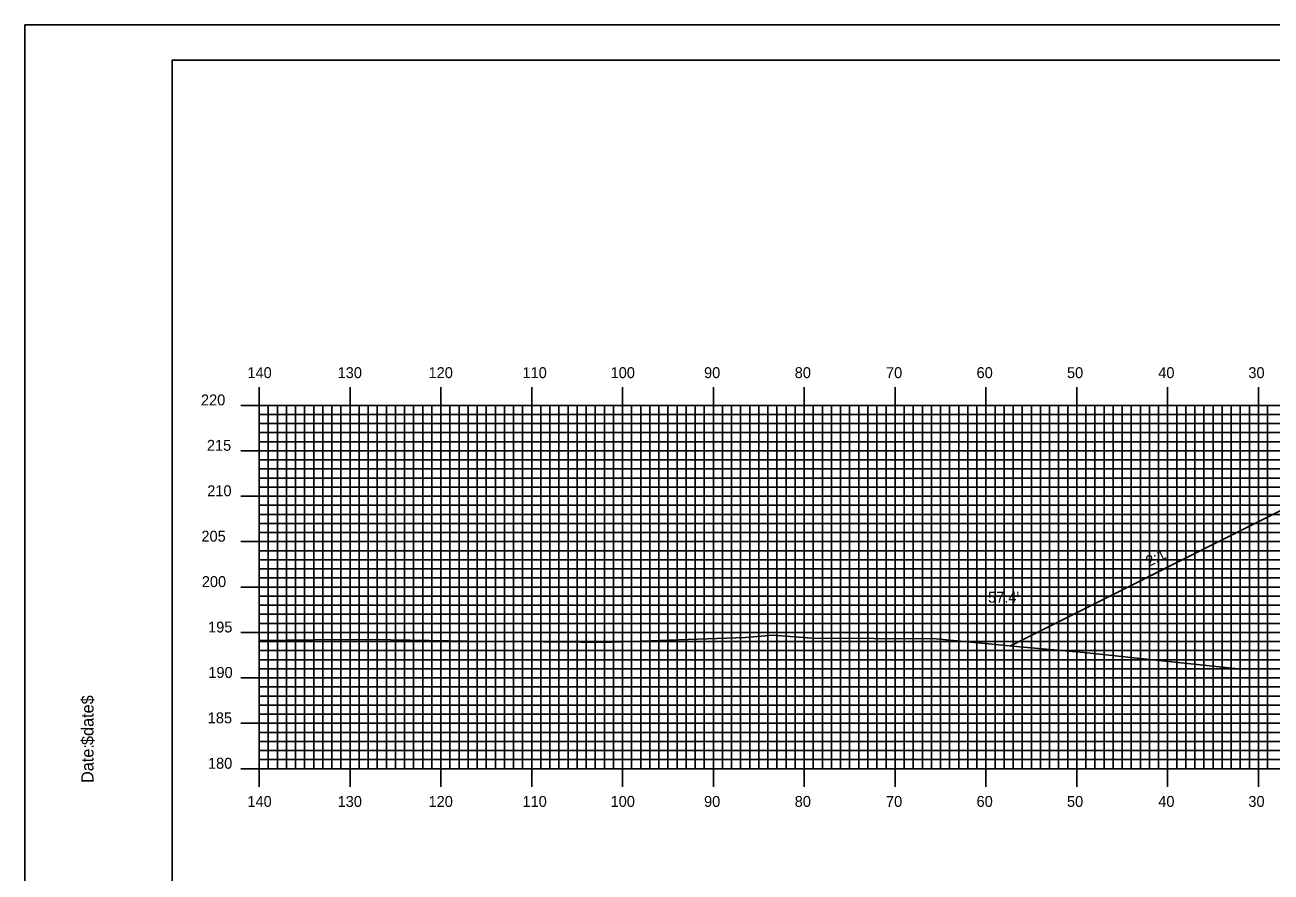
# Model space of a CAD drawing. Extents: x 1812948 to 1813291, y 442591 to 442811.
# Drawn here: x 1812947.7 to 1813084.9, y 442717.3 to 442810.5 of the extents above; entities that cross this region are included whole.
import ezdxf

# ---------------------------------------------------------------- set-up
doc = ezdxf.new("R2010")
doc.units = 0
for name, color, linetype in [('ANNOTATION', 7, 'Continuous'), ('BORDER', 7, 'Continuous'), ('D_Roadway_Centerline', 7, 'Continuous'), ('D_Roadway_SlopeLines', 7, 'Continuous'), ('D_Text_Standard', 7, 'Continuous'), ('H_V ANNOTATION', 7, 'Continuous'), ('MAJOR', 7, 'Continuous'), ('MINOR', 7, 'Continuous'), ('PLOT BOUNDARY', 7, 'Continuous'), ('S_Roadway_Centerline', 7, 'Continuous')]:
    doc.layers.add(name, color=color, linetype=linetype)

msp = doc.modelspace()

# ---------------------------------------------------------------- linework, layer by layer
at = {"layer": 'BORDER'}
msp.add_lwpolyline([(1812963.86, 442596.67), (1813283.86, 442596.67), (1813283.86, 442806.67), (1812963.86, 442806.67)], close=True, dxfattribs=at)
at = {"layer": 'D_Roadway_Centerline'}
msp.add_lwpolyline([(1813056.1, 442742.18), (1813085.25, 442756.76), (1813090.46, 442759.36), (1813093.46, 442759.42), (1813101.46, 442759.58), (1813113.46, 442759.01), (1813125.46, 442758.43), (1813133.46, 442758.05), (1813136.46, 442757.9), (1813141.99, 442755.14), (1813175.76, 442738.25)], dxfattribs=at)
at = {"layer": 'D_Roadway_SlopeLines'}
msp.add_lwpolyline([(1813090.46, 442759.36), (1813056.1, 442742.18)], dxfattribs=at)
at = {"layer": 'MAJOR'}
for p, q in [((1812973.46, 442770.67), (1812973.46, 442768.67)), ((1812983.46, 442770.67), (1812983.46, 442768.67)), ((1812993.46, 442770.67), (1812993.46, 442768.67)), ((1813003.46, 442770.67), (1813003.46, 442768.67)), ((1813013.46, 442770.67), (1813013.46, 442768.67)), ((1813023.46, 442770.67), (1813023.46, 442768.67)), ((1813033.46, 442770.67), (1813033.46, 442768.67)), ((1813043.46, 442770.67), (1813043.46, 442768.67)), ((1813053.46, 442770.67), (1813053.46, 442768.67)), ((1813063.46, 442770.67), (1813063.46, 442768.67)), ((1813073.46, 442770.67), (1813073.46, 442768.67)), ((1813083.46, 442770.67), (1813083.46, 442768.67)), ((1812971.45, 442768.67), (1812973.46, 442768.67)), ((1812973.46, 442768.67), (1813253.46, 442768.67)), ((1812973.46, 442728.67), (1812973.46, 442768.67)), ((1812973.46, 442728.67), (1812973.46, 442768.67)), ((1812973.46, 442768.67), (1813253.46, 442768.67)), ((1812983.46, 442728.67), (1812983.46, 442768.67)), ((1812993.46, 442728.67), (1812993.46, 442768.67)), ((1813003.46, 442728.67), (1813003.46, 442768.67)), ((1813013.46, 442728.67), (1813013.46, 442768.67)), ((1813023.46, 442728.67), (1813023.46, 442768.67)), ((1813033.46, 442728.67), (1813033.46, 442768.67)), ((1813043.46, 442728.67), (1813043.46, 442768.67)), ((1813053.46, 442728.67), (1813053.46, 442768.67)), ((1813063.46, 442728.67), (1813063.46, 442768.67)), ((1813073.46, 442728.67), (1813073.46, 442768.67)), ((1813083.46, 442728.67), (1813083.46, 442768.67)), ((1812971.45, 442763.67), (1812973.46, 442763.67)), ((1812973.46, 442763.67), (1813253.46, 442763.67)), ((1812971.45, 442758.67), (1812973.46, 442758.67)), ((1812973.46, 442758.67), (1813253.46, 442758.67)), ((1812971.45, 442753.67), (1812973.46, 442753.67)), ((1812973.46, 442753.67), (1813253.46, 442753.67)), ((1812971.45, 442748.67), (1812973.46, 442748.67)), ((1812973.46, 442748.67), (1813253.46, 442748.67)), ((1812971.45, 442743.67), (1812973.46, 442743.67)), ((1812973.46, 442743.67), (1813253.46, 442743.67)), ((1812971.45, 442738.67), (1812973.46, 442738.67)), ((1812973.46, 442738.67), (1813253.46, 442738.67)), ((1812971.45, 442733.67), (1812973.46, 442733.67)), ((1812973.46, 442733.67), (1813253.46, 442733.67)), ((1812971.45, 442728.67), (1812973.46, 442728.67)), ((1812973.46, 442728.67), (1813253.46, 442728.67)), ((1812973.46, 442728.67), (1813253.46, 442728.67)), ((1812973.46, 442726.66), (1812973.46, 442728.67)), ((1812983.46, 442726.66), (1812983.46, 442728.67)), ((1812993.46, 442726.66), (1812993.46, 442728.67)), ((1813003.46, 442726.66), (1813003.46, 442728.67)), ((1813013.46, 442726.66), (1813013.46, 442728.67)), ((1813023.46, 442726.66), (1813023.46, 442728.67)), ((1813033.46, 442726.66), (1813033.46, 442728.67)), ((1813043.46, 442726.66), (1813043.46, 442728.67)), ((1813053.46, 442726.66), (1813053.46, 442728.67)), ((1813063.46, 442726.66), (1813063.46, 442728.67)), ((1813073.46, 442726.66), (1813073.46, 442728.67)), ((1813083.46, 442726.66), (1813083.46, 442728.67))]:
    msp.add_line(p, q, dxfattribs=at)
at = {"layer": 'MINOR'}
for p, q in [((1812973.46, 442767.67), (1813253.46, 442767.67)), ((1812973.46, 442767.67), (1812975.46, 442767.67)), ((1812974.46, 442728.67), (1812974.46, 442768.67)), ((1812975.46, 442728.67), (1812975.46, 442768.67)), ((1812976.46, 442728.67), (1812976.46, 442768.67)), ((1812977.46, 442728.67), (1812977.46, 442768.67)), ((1812978.46, 442728.67), (1812978.46, 442768.67)), ((1812979.46, 442728.67), (1812979.46, 442768.67)), ((1812980.46, 442728.67), (1812980.46, 442768.67)), ((1812981.46, 442728.67), (1812981.46, 442768.67)), ((1812982.46, 442728.67), (1812982.46, 442768.67)), ((1812984.46, 442728.67), (1812984.46, 442768.67)), ((1812985.46, 442728.67), (1812985.46, 442768.67)), ((1812986.46, 442728.67), (1812986.46, 442768.67)), ((1812987.46, 442728.67), (1812987.46, 442768.67)), ((1812988.46, 442728.67), (1812988.46, 442768.67)), ((1812989.46, 442728.67), (1812989.46, 442768.67)), ((1812990.46, 442728.67), (1812990.46, 442768.67)), ((1812991.46, 442728.67), (1812991.46, 442768.67)), ((1812992.46, 442728.67), (1812992.46, 442768.67)), ((1812994.46, 442728.67), (1812994.46, 442768.67)), ((1812995.46, 442728.67), (1812995.46, 442768.67)), ((1812996.46, 442728.67), (1812996.46, 442768.67)), ((1812997.46, 442728.67), (1812997.46, 442768.67)), ((1812998.46, 442728.67), (1812998.46, 442768.67)), ((1812999.46, 442728.67), (1812999.46, 442768.67)), ((1813000.46, 442728.67), (1813000.46, 442768.67)), ((1813001.46, 442728.67), (1813001.46, 442768.67)), ((1813002.46, 442728.67), (1813002.46, 442768.67)), ((1813004.46, 442728.67), (1813004.46, 442768.67)), ((1813005.46, 442728.67), (1813005.46, 442768.67)), ((1813006.46, 442728.67), (1813006.46, 442768.67)), ((1813007.46, 442728.67), (1813007.46, 442768.67)), ((1813008.46, 442728.67), (1813008.46, 442768.67)), ((1813009.46, 442728.67), (1813009.46, 442768.67)), ((1813010.46, 442728.67), (1813010.46, 442768.67)), ((1813011.46, 442728.67), (1813011.46, 442768.67)), ((1813012.46, 442728.67), (1813012.46, 442768.67)), ((1813014.46, 442728.67), (1813014.46, 442768.67)), ((1813015.46, 442728.67), (1813015.46, 442768.67)), ((1813016.46, 442728.67), (1813016.46, 442768.67)), ((1813017.46, 442728.67), (1813017.46, 442768.67)), ((1813018.46, 442728.67), (1813018.46, 442768.67)), ((1813019.46, 442728.67), (1813019.46, 442768.67)), ((1813020.46, 442728.67), (1813020.46, 442768.67)), ((1813021.46, 442728.67), (1813021.46, 442768.67)), ((1813022.46, 442728.67), (1813022.46, 442768.67)), ((1813024.46, 442728.67), (1813024.46, 442768.67)), ((1813025.46, 442728.67), (1813025.46, 442768.67)), ((1813026.46, 442728.67), (1813026.46, 442768.67)), ((1813027.46, 442728.67), (1813027.46, 442768.67)), ((1813028.46, 442728.67), (1813028.46, 442768.67)), ((1813029.46, 442728.67), (1813029.46, 442768.67)), ((1813030.46, 442728.67), (1813030.46, 442768.67)), ((1813031.46, 442728.67), (1813031.46, 442768.67)), ((1813032.46, 442728.67), (1813032.46, 442768.67)), ((1813034.46, 442728.67), (1813034.46, 442768.67)), ((1813035.46, 442728.67), (1813035.46, 442768.67)), ((1813036.46, 442728.67), (1813036.46, 442768.67)), ((1813037.46, 442728.67), (1813037.46, 442768.67)), ((1813038.46, 442728.67), (1813038.46, 442768.67)), ((1813039.46, 442728.67), (1813039.46, 442768.67)), ((1813040.46, 442728.67), (1813040.46, 442768.67)), ((1813041.46, 442728.67), (1813041.46, 442768.67)), ((1813042.46, 442728.67), (1813042.46, 442768.67)), ((1813044.46, 442728.67), (1813044.46, 442768.67)), ((1813045.46, 442728.67), (1813045.46, 442768.67)), ((1813046.46, 442728.67), (1813046.46, 442768.67)), ((1813047.46, 442728.67), (1813047.46, 442768.67)), ((1813048.46, 442728.67), (1813048.46, 442768.67)), ((1813049.46, 442728.67), (1813049.46, 442768.67)), ((1813050.46, 442728.67), (1813050.46, 442768.67)), ((1813051.46, 442728.67), (1813051.46, 442768.67)), ((1813052.46, 442728.67), (1813052.46, 442768.67)), ((1813054.46, 442728.67), (1813054.46, 442768.67)), ((1813055.46, 442728.67), (1813055.46, 442768.67)), ((1813056.46, 442728.67), (1813056.46, 442768.67)), ((1813057.46, 442728.67), (1813057.46, 442768.67)), ((1813058.46, 442728.67), (1813058.46, 442768.67)), ((1813059.46, 442728.67), (1813059.46, 442768.67)), ((1813060.46, 442728.67), (1813060.46, 442768.67)), ((1813061.46, 442728.67), (1813061.46, 442768.67)), ((1813062.46, 442728.67), (1813062.46, 442768.67)), ((1813064.46, 442728.67), (1813064.46, 442768.67)), ((1813065.46, 442728.67), (1813065.46, 442768.67)), ((1813066.46, 442728.67), (1813066.46, 442768.67)), ((1813067.46, 442728.67), (1813067.46, 442768.67)), ((1813068.46, 442728.67), (1813068.46, 442768.67)), ((1813069.46, 442728.67), (1813069.46, 442768.67)), ((1813070.46, 442728.67), (1813070.46, 442768.67)), ((1813071.46, 442728.67), (1813071.46, 442768.67)), ((1813072.46, 442728.67), (1813072.46, 442768.67)), ((1813074.46, 442728.67), (1813074.46, 442768.67)), ((1813075.46, 442728.67), (1813075.46, 442768.67)), ((1813076.46, 442728.67), (1813076.46, 442768.67)), ((1813077.46, 442728.67), (1813077.46, 442768.67)), ((1813078.46, 442728.67), (1813078.46, 442768.67)), ((1813079.46, 442728.67), (1813079.46, 442768.67)), ((1813080.46, 442728.67), (1813080.46, 442768.67)), ((1813081.46, 442728.67), (1813081.46, 442768.67)), ((1813082.46, 442728.67), (1813082.46, 442768.67)), ((1813084.46, 442728.67), (1813084.46, 442768.67)), ((1812973.46, 442766.67), (1813253.46, 442766.67)), ((1812973.46, 442766.67), (1812975.46, 442766.67)), ((1812973.46, 442765.67), (1813253.46, 442765.67)), ((1812973.46, 442765.67), (1812975.46, 442765.67)), ((1812973.46, 442764.67), (1813253.46, 442764.67)), ((1812973.46, 442764.67), (1812975.46, 442764.67)), ((1812973.46, 442762.67), (1813253.46, 442762.67)), ((1812973.46, 442762.67), (1812975.46, 442762.67)), ((1812973.46, 442761.67), (1813253.46, 442761.67)), ((1812973.46, 442761.67), (1812975.46, 442761.67)), ((1812973.46, 442760.67), (1813253.46, 442760.67)), ((1812973.46, 442760.67), (1812975.46, 442760.67)), ((1812973.46, 442759.67), (1813253.46, 442759.67)), ((1812973.46, 442759.67), (1812975.46, 442759.67)), ((1812973.46, 442757.67), (1813253.46, 442757.67)), ((1812973.46, 442757.67), (1812975.46, 442757.67)), ((1812973.46, 442756.67), (1813253.46, 442756.67)), ((1812973.46, 442756.67), (1812975.46, 442756.67)), ((1812973.46, 442755.67), (1813253.46, 442755.67)), ((1812973.46, 442755.67), (1812975.46, 442755.67)), ((1812973.46, 442754.67), (1813253.46, 442754.67)), ((1812973.46, 442754.67), (1812975.46, 442754.67)), ((1812973.46, 442752.67), (1813253.46, 442752.67)), ((1812973.46, 442752.67), (1812975.46, 442752.67)), ((1812973.46, 442751.67), (1813253.46, 442751.67)), ((1812973.46, 442751.67), (1812975.46, 442751.67)), ((1812973.46, 442750.67), (1813253.46, 442750.67)), ((1812973.46, 442750.67), (1812975.46, 442750.67)), ((1812973.46, 442749.67), (1813253.46, 442749.67)), ((1812973.46, 442749.67), (1812975.46, 442749.67)), ((1812973.46, 442747.67), (1813253.46, 442747.67)), ((1812973.46, 442747.67), (1812975.46, 442747.67)), ((1812973.46, 442746.67), (1813253.46, 442746.67)), ((1812973.46, 442746.67), (1812975.46, 442746.67)), ((1812973.46, 442745.67), (1813253.46, 442745.67)), ((1812973.46, 442745.67), (1812975.46, 442745.67)), ((1812973.46, 442744.67), (1813253.46, 442744.67)), ((1812973.46, 442744.67), (1812975.46, 442744.67)), ((1812973.46, 442742.67), (1813253.46, 442742.67)), ((1812973.46, 442742.67), (1812975.46, 442742.67)), ((1812973.46, 442741.67), (1813253.46, 442741.67)), ((1812973.46, 442741.67), (1812975.46, 442741.67)), ((1812973.46, 442740.67), (1813253.46, 442740.67)), ((1812973.46, 442740.67), (1812975.46, 442740.67)), ((1812973.46, 442739.67), (1813253.46, 442739.67)), ((1812973.46, 442739.67), (1812975.46, 442739.67)), ((1812973.46, 442737.67), (1813253.46, 442737.67)), ((1812973.46, 442737.67), (1812975.46, 442737.67)), ((1812973.46, 442736.67), (1813253.46, 442736.67)), ((1812973.46, 442736.67), (1812975.46, 442736.67)), ((1812973.46, 442735.67), (1813253.46, 442735.67)), ((1812973.46, 442735.67), (1812975.46, 442735.67)), ((1812973.46, 442734.67), (1813253.46, 442734.67)), ((1812973.46, 442734.67), (1812975.46, 442734.67)), ((1812973.46, 442732.67), (1813253.46, 442732.67)), ((1812973.46, 442732.67), (1812975.46, 442732.67)), ((1812973.46, 442731.67), (1813253.46, 442731.67)), ((1812973.46, 442731.67), (1812975.46, 442731.67)), ((1812973.46, 442730.67), (1813253.46, 442730.67)), ((1812973.46, 442730.67), (1812975.46, 442730.67)), ((1812973.46, 442729.67), (1813253.46, 442729.67)), ((1812973.46, 442729.67), (1812975.46, 442729.67))]:
    msp.add_line(p, q, dxfattribs=at)
at = {"layer": 'PLOT BOUNDARY'}
msp.add_lwpolyline([(1812947.67, 442590.55), (1813287.67, 442590.55), (1813287.67, 442810.55), (1812947.67, 442810.55)], close=True, dxfattribs=at)
at = {"layer": 'S_Roadway_Centerline'}
msp.add_lwpolyline([(1812973.46, 442742.78), (1812979.6, 442742.85), (1812985.83, 442742.89), (1812996.41, 442742.72), (1813008.92, 442742.62), (1813012.27, 442742.59), (1813026.99, 442743.13), (1813030.01, 442743.39), (1813034.31, 442743.06), (1813047.99, 442742.98), (1813057.2, 442742.08), (1813064.23, 442741.47), (1813080.18, 442739.76), (1813080.9, 442739.69), (1813081.34, 442739.66), (1813083.62, 442739.65), (1813095.98, 442739.66)], dxfattribs=at)

# ---------------------------------------------------------------- texts
at = {"layer": 'ANNOTATION'}
msp.add_text('2:1', height=1.2, rotation=26.5651, dxfattribs=at).set_placement((1813071.42, 442750.88))
at = {"layer": 'BORDER'}
for s, p in [('$date$', (1812955.22, 442731.28)), ('Date:', (1812955.22, 442727.1))]:
    msp.add_text(s, height=1.339, rotation=90, dxfattribs=at).set_placement(p)
at = {"layer": 'D_Text_Standard'}
msp.add_text("57.4'", height=1.2, dxfattribs=at).set_placement((1813053.69, 442746.95))
at = {"layer": 'H_V ANNOTATION'}
for s, p in [('140', (1812972.16, 442771.67)), ('130', (1812982.09, 442771.67)), ('120', (1812992.1, 442771.67)), ('110', (1813002.44, 442771.67)), ('100', (1813012.14, 442771.67)), ('90', (1813022.43, 442771.67)), ('80', (1813032.41, 442771.67)), ('70', (1813042.46, 442771.67)), ('60', (1813052.43, 442771.67)), ('50', (1813062.38, 442771.67)), ('40', (1813072.43, 442771.67)), ('30', (1813082.35, 442771.67)), ('220', (1812967.05, 442768.67)), ('215', (1812967.7, 442763.67)), ('210', (1812967.74, 442758.67)), ('205', (1812967.1, 442753.67)), ('200', (1812967.14, 442748.67)), ('195', (1812967.83, 442743.67)), ('190', (1812967.86, 442738.67)), ('185', (1812967.79, 442733.67)), ('180', (1812967.82, 442728.67)), ('140', (1812972.16, 442724.47)), ('130', (1812982.09, 442724.47)), ('120', (1812992.1, 442724.47)), ('110', (1813002.44, 442724.47)), ('100', (1813012.14, 442724.47)), ('90', (1813022.43, 442724.47)), ('80', (1813032.41, 442724.47)), ('70', (1813042.46, 442724.47)), ('60', (1813052.43, 442724.47)), ('50', (1813062.38, 442724.47)), ('40', (1813072.43, 442724.47)), ('30', (1813082.35, 442724.47))]:
    msp.add_text(s, height=1.2, dxfattribs=at).set_placement(p)
at = {"layer": 'MAJOR'}
msp.add_text('-', height=0.012, dxfattribs=at).set_placement((1812973.45, 442728.67))

doc.saveas('drawing.dxf')
